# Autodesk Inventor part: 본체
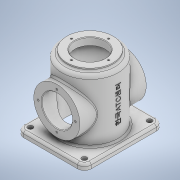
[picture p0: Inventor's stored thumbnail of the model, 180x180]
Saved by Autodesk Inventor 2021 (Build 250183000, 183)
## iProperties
Created: 2021-02
Part Number: 본체
Material: 알루미늄 6061
Document SubType Name: Modeling
Designer: 201-05
Density: 2.7 g/cm^3
Appearance: 기본값
Mass: 1232.13 g
Surface Area: 1068.87 cm^2
Volume: 456.344 cm^3
Author: 201-05
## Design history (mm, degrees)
sketch "스케치1"
  geometry: L1 (60, 70)-(-60, 70); L2 (-60, 70)-(-60, -70); L3 (-60, -70)-(60, -70); L4 (60, -70)-(60, 70); L5 (60, 70)-(-60, -70); L6 (-60, 70)-(60, -70); 1 further point
  constraints: 12 end point, 2 midpoint, 2 parallel, 1 horizontal, 1 perpendicular
  dimensions: "d0" = 120 distance of L3.end L2.end; "d1" = 140 distance of L2.end L1.end
extrude "돌출1" new body sketch "스케치1" distance "d2" = 10; taper "d3" = 0 deg
sketch "스케치2"
  geometry: C1 r 50 at (0, 0); 1 further point
  constraints: 1 centre point, 1 coincident
  dimensions: "d4" = 100 diameter of C1
extrude "돌출2" join sketch "스케치2" distance "d5" = 110; taper "d6" = 0 deg
sketch "스케치3"
  geometry: C1 r 41 at (0, 0); 1 further point
  constraints: 1 centre point, 1 coincident
  dimensions: "d7" = 82 diameter of C1
extrude "돌출3" join sketch "스케치3" distance "d8" = 5; taper "d9" = 0 deg
sketch "스케치4"
  geometry: C1 r 27 at (0, 0); 1 further point
  constraints: 1 centre point, 1 coincident
  dimensions: "d10" = 54 diameter of C1
extrude "돌출4" cut sketch "스케치4" extent not by distance; stored distance "d11" = 100; taper "d12" = 0 deg
sketch "스케치6"
  geometry: C1 r 41 at (0, 60); 1 further point
  constraints: 1 centre point
  dimensions: "d16" = 82 diameter of C1; "d67" = 60 distance of point (0, 0) C1.centre
extrude "돌출6" join sketch "스케치6" stored distance "d17" = 118; taper "d18" = 0 deg
sketch "스케치7"
  geometry: C1 r 27 at (0, 0); 1 further point
  constraints: 1 centre point
  dimensions: "d19" = 54 diameter of C1
extrude "돌출7" cut sketch "스케치7" extent not by distance; stored distance "d20" = 0; taper "d21" = 0 deg
sketch "스케치5"
  geometry: C1 r 42 at (0, 0); 1 further point
  constraints: 1 centre point, 1 coincident
  dimensions: "d13" = 84 diameter of C1
extrude "돌출5" cut sketch "스케치5" distance "d14" = 112; taper "d15" = 0 deg
sketch "스케치8"
  geometry: A1 r 33 centre (0, 0) between (-33, 0) and (0, 33); 3 further points
  constraints: 4 point on circle, 2 horizontal alignment, 2 vertical alignment, 1 centre point, 1 coincident
  dimensions: "d22" = 66 diameter of A1
hole "구멍1" sketch "스케치8" at (-33, 0), (0, 33), (33, 0), (0, -33) diameter "d23" = 3.242; stored, may be unused: countersink angle "d27" = 90 deg, drill point angle "d29" = 118 deg; dims "d24" = 8, "d25" = 4, "d26" = 2, "d28" = 10
sketch "스케치9"
  geometry: L1 (0, -75.803)-(0, 75.803); L2 (-57.676, 0)-(60.972, 0); C1 r 27 at (0, 0) reference; A1 r 33 centre (0, 0) between (0, 33) and (-33, 0); 4 further points
  constraints: 4 end point, 4 point on circle, 2 horizontal alignment, 2 midpoint, 2 point on line, 2 vertical alignment, 1 centre point, 1 coincident, 1 horizontal, 1 vertical
  dimensions: "d30" = 66 diameter of A1
hole "구멍2" sketch "스케치9" at (0, 33), (-33, 0), (0, -33), (33, 0) diameter "d31" = 3.242; stored, may be unused: countersink angle "d35" = 90 deg, drill point angle "d37" = 118 deg; dims "d32" = 8, "d33" = 4, "d34" = 2, "d36" = 10
sketch "스케치10"
  geometry: L1 (60, 70)-(-60, 70) reference; L2 (60, -70)-(60, 70) reference; L3 (-60, 70)-(-60, -70) reference; L4 (-60, -70)-(60, -70) reference; C1 r 4.5 at (48, 58); C2 r 4.5 at (48, -58); C3 r 4.5 at (-48, -58); C4 r 4.5 at (-48, 58); 1 further point
  constraints: 4 centre point, 2 horizontal alignment, 2 vertical alignment
  dimensions: "d38" = 9 diameter of C1; "d39" = 9 diameter of C2; "d40" = 9 diameter of C3; "d41" = 9 diameter of C4; "d42" = 12 distance from line of L1 C1.centre; "d43" = 12 distance from line of L2 C1.centre; "d44" = 12 distance from line of L3 C3.centre; "d45" = 12 distance from line of L4 C3.centre
extrude "돌출8" cut sketch "스케치10" extent not by distance; stored distance "d46" = 0; taper "d47" = 0 deg
node "작업 평면2"
sketch "스케치12"
  geometry: L1 (120, -50)-(120, 50) reference; L2 (10, 50)-(10, -50) reference; L3 (163.739, 0)-(-33.956, 0); 2 further points
  constraints: 2 end point, 1 horizontal, 1 midpoint, 1 point on line
sketch "스케치11"
  geometry: L1 (163.739, 0)-(-33.956, 0) reference; 3 further points
  constraints: 1 horizontal alignment, 1 midpoint, 1 other
  dimensions: "d50" = 66 distance of point (0, 0) point (66, 0)
feature "엠보싱1" sketch "스케치11" dims "d0" = 120, "d1" = 140, "d10" = 54, "d51" = 0.5, "d52" = 0
fillet "모깎기7" dims "d65" = 12
fillet "모깎기3" dims "d55" = 3
fillet "모깎기4" dims "d56" = 6
fillet "모깎기5" dims "d57" = 3
chamfer "모따기1" distance "d58" = 1; stored, may be unused: second distance "d59" = 2, angle "d60" = 45 deg
fillet "모깎기6" dims "d61" = 3
chamfer "모따기2" distance "d62" = 1; stored, may be unused: second distance "d63" = 2, angle "d64" = 45 deg
fillet "모깎기8" dims "d66" = 4
node "솔리드1"
mirror "미러1"
feature "A9D066F2-1C7D-4E18-AEED-F7BC21143FA4" dims "d23" = 3.242, "d24" = 8, "d25" = 4, "d26" = 2, "d27" = 90 deg, "d28" = 10, "d29" = 118 deg
other parameters: "d49" = 127.5
